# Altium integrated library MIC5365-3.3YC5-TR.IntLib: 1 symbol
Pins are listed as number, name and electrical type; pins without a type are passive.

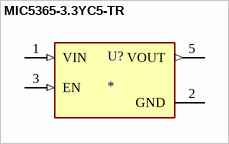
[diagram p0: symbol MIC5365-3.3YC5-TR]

## MIC5365-3.3YC5-TR
designator U?
Linear Voltage Regulator IC Positive Fixed 1 Output 150mA SC-70-5; MF: Microchip; MP: MIC5365-3.3YC5-TR
footprint SOT65P210X110-5N
pins: 1 VIN (in), 2 GND (power), 3 EN (in), 5 VOUT (out)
